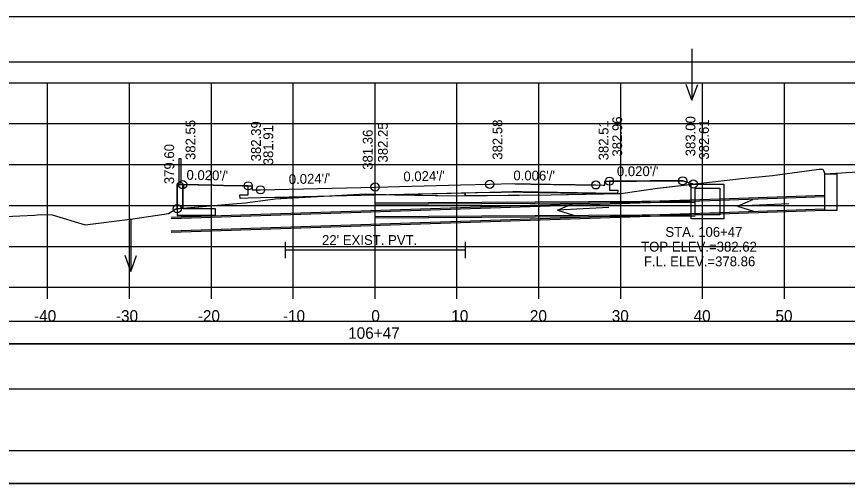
# Model space of a CAD drawing. Extents: x -37291014 to -37290680, y -936053 to -933067.
# Drawn here: x -37290886.9 to -37290785.4, y -934559.9 to -934502.9 of the extents above; entities that cross this region are included whole.
import ezdxf

# ---------------------------------------------------------------- set-up
doc = ezdxf.new("R2010")
doc.units = 0
for name, color, linetype in [('Default', 7, 'Continuous'), ('R_Alt Surface', 7, 'Continuous'), ('R_Axis', 7, 'Continuous'), ('R_Axis Annot', 7, 'Continuous'), ('R_Border', 7, 'Continuous'), ('R_Contours', 7, 'Continuous'), ('R_Exist Surface', 7, 'Continuous'), ('R_Fin Surface', 7, 'Continuous'), ('R_Grid', 7, 'Continuous'), ('R_No Plot', 7, 'Continuous'), ('R_Water', 7, 'Continuous'), ('R_Water Annot', 7, 'Continuous'), ('R_Xsect Elev', 7, 'Continuous'), ('R_Xsect Slope', 7, 'Continuous')]:
    doc.layers.add(name, color=color, linetype=linetype)

msp = doc.modelspace()

# ---------------------------------------------------------------- linework, layer by layer
at = {"layer": 'Default'}
for p, q in [((-37290867.02, -934523.22), (-37290867.02, -934520.22)), ((-37290867.02, -934520.22), (-37290866.85, -934520.22)), ((-37290866.85, -934520.22), (-37290866.85, -934523.22)), ((-37290867.21, -934523.24), (-37290867.27, -934523.3)), ((-37290867.27, -934523.3), (-37290867.27, -934527.19)), ((-37290866.66, -934523.22), (-37290867.21, -934523.22)), ((-37290867.21, -934523.22), (-37290867.21, -934523.24)), ((-37290866.66, -934523.24), (-37290867.21, -934523.24)), ((-37290866.66, -934523.24), (-37290866.66, -934523.22)), ((-37290866.6, -934523.3), (-37290866.66, -934523.24)), ((-37290866.6, -934526.36), (-37290866.6, -934523.3)), ((-37290862.6, -934526.36), (-37290866.6, -934526.36)), ((-37290862.6, -934527.19), (-37290862.6, -934526.36)), ((-37290862.6, -934527.19), (-37290867.27, -934527.19))]:
    msp.add_line(p, q, dxfattribs=at)
for points in [[(-37290992.58, -934508.41), (-37290694.16, -934508.41), (-37290694.16, -934502.89), (-37290992.58, -934502.89)], [(-37290992.31, -934542.86), (-37290693.89, -934542.86), (-37290693.89, -934540.16), (-37290992.31, -934540.16)], [(-37290992.31, -934548.39), (-37290693.89, -934548.39), (-37290693.89, -934542.86), (-37290992.31, -934542.86)]]:
    msp.add_lwpolyline(points, close=True, dxfattribs=at)
msp.add_lwpolyline([(-37290866.52, -934523.91), (-37290866.6, -934523.91), (-37290866.6, -934523.41), (-37290866.52, -934523.41), (-37290866.52, -934523.91)], dxfattribs=at)
at = {"layer": 'R_Alt Surface'}
for points in [[(-37290829.1, -934524.37), (-37290843.1, -934524.71), (-37290857.1, -934525.05), (-37290858.6, -934525.08), (-37290859.6, -934525.1), (-37290859.61, -934524.68), (-37290858.6, -934524.66), (-37290858.6, -934523.57)], [(-37290826.27, -934524.29), (-37290826.27, -934524.29), (-37290826.27, -934524.29), (-37290826.27, -934524.29), (-37290826.27, -934524.29), (-37290829.1, -934524.37), (-37290843.1, -934524.71), (-37290857.1, -934525.05), (-37290858.6, -934525.08), (-37290859.6, -934525.1), (-37290859.61, -934524.68), (-37290858.6, -934524.66), (-37290858.6, -934523.57)], [(-37290814.47, -934522.99), (-37290814.47, -934524.09), (-37290813.46, -934524.11), (-37290813.47, -934524.52), (-37290814.48, -934524.5)], [(-37290829.1, -934524.37), (-37290826.27, -934524.29), (-37290826, -934524.3), (-37290825.78, -934524.3), (-37290825.77, -934524.3), (-37290825.59, -934524.3), (-37290825.49, -934524.31), (-37290825.47, -934524.31), (-37290825.18, -934524.31), (-37290825.12, -934524.31), (-37290825.01, -934524.32), (-37290824.82, -934524.32), (-37290824.62, -934524.32), (-37290824.42, -934524.33), (-37290824.17, -934524.33), (-37290824.06, -934524.34), (-37290823.97, -934524.34), (-37290823.47, -934524.35), (-37290823.46, -934524.35), (-37290823.25, -934524.35), (-37290823.22, -934524.35), (-37290822.92, -934524.36), (-37290822.8, -934524.36), (-37290822.32, -934524.37), (-37290822.26, -934524.37), (-37290822.08, -934524.37), (-37290821.66, -934524.38), (-37290821.3, -934524.39), (-37290821.17, -934524.39), (-37290820.94, -934524.39), (-37290820.82, -934524.39), (-37290820.46, -934524.4), (-37290820.15, -934524.4), (-37290819.99, -934524.41), (-37290819.55, -934524.41), (-37290819.29, -934524.42), (-37290818.71, -934524.42), (-37290818.57, -934524.43), (-37290818.36, -934524.43), (-37290817.51, -934524.44), (-37290817.35, -934524.44), (-37290817.32, -934524.44), (-37290816.38, -934524.45), (-37290816.25, -934524.45), (-37290816.14, -934524.45), (-37290814.48, -934524.5)], [(-37290854.1, -934530.39), (-37290854.1, -934532.39)], [(-37290832.1, -934530.39), (-37290832.1, -934532.39)], [(-37290854.1, -934531.39), (-37290832.1, -934531.39)]]:
    msp.add_lwpolyline(points, dxfattribs=at)
at = {"layer": 'R_Axis'}
for p, q in [((-37290993.1, -934535.96), (-37290693.1, -934535.96)), ((-37290883.1, -934537.36), (-37290883.1, -934535.96)), ((-37290873.1, -934537.36), (-37290873.1, -934535.96)), ((-37290863.1, -934537.36), (-37290863.1, -934535.96)), ((-37290853.1, -934537.36), (-37290853.1, -934535.96)), ((-37290843.1, -934537.36), (-37290843.1, -934535.96)), ((-37290833.1, -934537.36), (-37290833.1, -934535.96)), ((-37290823.1, -934537.36), (-37290823.1, -934535.96)), ((-37290813.1, -934537.36), (-37290813.1, -934535.96)), ((-37290803.1, -934537.36), (-37290803.1, -934535.96)), ((-37290793.1, -934537.36), (-37290793.1, -934535.96))]:
    msp.add_line(p, q, dxfattribs=at)
at = {"layer": 'R_Border'}
msp.add_line((-37290684.92, -934555.96), (-37291001.1, -934555.96), dxfattribs=at)
at = {"layer": 'R_Contours'}
for p, q in [((-37290866.6, -934523.91), (-37290866.6, -934526.3)), ((-37290854.1, -934525.09), (-37290850.22, -934524.88)), ((-37290850.22, -934524.88), (-37290854.1, -934524.97)), ((-37290832.1, -934524.45), (-37290840.69, -934524.65)), ((-37290829.1, -934524.37), (-37290832.1, -934524.45)), ((-37290832.1, -934524.76), (-37290832.1, -934524.45)), ((-37290832.1, -934524.45), (-37290832.1, -934524.76)), ((-37290813.97, -934524.51), (-37290814.48, -934524.5)), ((-37290813.47, -934524.5), (-37290813.97, -934524.51)), ((-37290813.97, -934524.51), (-37290813.47, -934524.52)), ((-37290813.47, -934524.5), (-37290813.09, -934524.5)), ((-37290813.47, -934524.52), (-37290813.47, -934524.5)), ((-37290854.1, -934524.97), (-37290854.1, -934525.09)), ((-37290854.1, -934525.09), (-37290854.1, -934524.97)), ((-37290866.6, -934526.3), (-37290867.27, -934526.36)), ((-37290866.6, -934526.36), (-37290866.6, -934526.3)), ((-37290862.6, -934526.36), (-37290866.6, -934526.36)), ((-37290862.6, -934527.19), (-37290862.6, -934526.36)), ((-37290867.27, -934527.19), (-37290862.6, -934527.19))]:
    msp.add_line(p, q, dxfattribs=at)
for points in [[(-37290866.52, -934523.41), (-37290866.52, -934523.91), (-37290866.6, -934523.91)], [(-37290858.6, -934523.57), (-37290859.35, -934523.55), (-37290861.6, -934523.51), (-37290862.85, -934523.48), (-37290866.52, -934523.41)], [(-37290854.1, -934524.97), (-37290857.1, -934525.05), (-37290858.6, -934525.08), (-37290859.6, -934525.1), (-37290859.61, -934524.68), (-37290858.6, -934524.66), (-37290858.6, -934523.57)], [(-37290804.25, -934523.35), (-37290804.3, -934523.33), (-37290804.39, -934523.3), (-37290804.4, -934523.3), (-37290804.47, -934523.28), (-37290804.49, -934523.27), (-37290805.26, -934523.04), (-37290805.52, -934522.95), (-37290808.25, -934522.97), (-37290808.32, -934522.97), (-37290808.48, -934522.97), (-37290808.88, -934522.97), (-37290809.51, -934522.97), (-37290811.16, -934522.98), (-37290812.1, -934522.98), (-37290812.27, -934522.98), (-37290812.33, -934522.98), (-37290812.59, -934522.98), (-37290812.66, -934522.99), (-37290814.47, -934522.99)], [(-37290814.47, -934522.99), (-37290814.47, -934524.09), (-37290813.46, -934524.11), (-37290813.47, -934524.5)], [(-37290813.09, -934524.5), (-37290808.6, -934523.86), (-37290804.25, -934523.35)], [(-37290804.25, -934523.35), (-37290804.25, -934523.35)], [(-37290840.69, -934524.65), (-37290833.31, -934524.77), (-37290832.1, -934524.76)], [(-37290832.1, -934524.76), (-37290821.61, -934524.66), (-37290813.97, -934524.51)], [(-37290814.48, -934524.5), (-37290816.14, -934524.45), (-37290816.25, -934524.45), (-37290816.38, -934524.45), (-37290817.32, -934524.44), (-37290817.35, -934524.44), (-37290817.51, -934524.44), (-37290818.36, -934524.43), (-37290818.57, -934524.43), (-37290818.71, -934524.42), (-37290819.29, -934524.42), (-37290819.55, -934524.41), (-37290819.99, -934524.41), (-37290820.15, -934524.4), (-37290820.46, -934524.4), (-37290820.82, -934524.39), (-37290820.94, -934524.39), (-37290821.17, -934524.39), (-37290821.3, -934524.39), (-37290821.66, -934524.38), (-37290822.08, -934524.37), (-37290822.26, -934524.37), (-37290822.32, -934524.37), (-37290822.8, -934524.36), (-37290822.92, -934524.36), (-37290823.22, -934524.35), (-37290823.25, -934524.35), (-37290823.46, -934524.35), (-37290823.47, -934524.35), (-37290823.97, -934524.34), (-37290824.06, -934524.34), (-37290824.17, -934524.33), (-37290824.42, -934524.33), (-37290824.62, -934524.32), (-37290824.82, -934524.32), (-37290825.01, -934524.32), (-37290825.12, -934524.31), (-37290825.18, -934524.31), (-37290825.47, -934524.31), (-37290825.49, -934524.31), (-37290825.59, -934524.3), (-37290825.78, -934524.3), (-37290826, -934524.3), (-37290826.27, -934524.29), (-37290829.1, -934524.37)], [(-37290866.6, -934526.3), (-37290859.98, -934525.72), (-37290858.87, -934525.63), (-37290858.63, -934525.6), (-37290855.31, -934525.15), (-37290854.1, -934525.09)], [(-37290867.27, -934526.36), (-37290867.27, -934526.45), (-37290867.27, -934527.19)]]:
    msp.add_lwpolyline(points, dxfattribs=at)
at = {"layer": 'R_Exist Surface'}
msp.add_lwpolyline([(-37290894.61, -934527.59), (-37290884.69, -934527.15), (-37290884.37, -934527.12), (-37290883.88, -934527.06), (-37290882.54, -934527.09), (-37290878.52, -934528.35), (-37290872.71, -934527.59), (-37290868.33, -934526.95), (-37290867.44, -934526.37), (-37290859.98, -934525.72), (-37290858.87, -934525.63), (-37290858.63, -934525.6), (-37290855.31, -934525.15), (-37290846.46, -934524.68), (-37290844.27, -934524.56), (-37290841.75, -934524.64), (-37290833.31, -934524.77), (-37290821.61, -934524.66), (-37290813.09, -934524.5), (-37290808.6, -934523.86), (-37290798.33, -934522.67), (-37290794.55, -934522.29), (-37290788.87, -934521.54), (-37290788.72, -934521.54), (-37290788.39, -934521.54), (-37290788.31, -934521.7), (-37290788.17, -934522.1), (-37290782.17, -934521.71)], dxfattribs=at)
msp.add_lwpolyline([(-37290894.61, -934527.59), (-37290884.69, -934527.15), (-37290884.37, -934527.12), (-37290883.88, -934527.06), (-37290882.54, -934527.09), (-37290878.52, -934528.35), (-37290872.71, -934527.59), (-37290868.33, -934526.95), (-37290867.44, -934526.37), (-37290859.98, -934525.72), (-37290858.87, -934525.63), (-37290858.63, -934525.6), (-37290855.31, -934525.15), (-37290846.46, -934524.68), (-37290844.27, -934524.56), (-37290841.75, -934524.64), (-37290833.31, -934524.77), (-37290821.61, -934524.66), (-37290813.09, -934524.5), (-37290808.6, -934523.86), (-37290798.33, -934522.67), (-37290794.55, -934522.29), (-37290788.87, -934521.54), (-37290788.72, -934521.54), (-37290788.39, -934521.54), (-37290788.31, -934521.7), (-37290788.17, -934522.1), (-37290782.17, -934521.71)], dxfattribs=at)
at = {"layer": 'R_Fin Surface'}
for points in [[(-37290867.27, -934526.45), (-37290867.27, -934525.6), (-37290867.27, -934523.41), (-37290866.77, -934523.41), (-37290866.6, -934523.41), (-37290862.85, -934523.48), (-37290861.6, -934523.51), (-37290859.35, -934523.55), (-37290858.6, -934523.57), (-37290858.48, -934523.57), (-37290858.1, -934523.57), (-37290858.1, -934523.69), (-37290858.1, -934524.07), (-37290857.35, -934524.05), (-37290857.1, -934524.05), (-37290846.61, -934523.8), (-37290843.1, -934523.71), (-37290832.61, -934523.46), (-37290829.1, -934523.37)], [(-37290829.1, -934523.37), (-37290826.27, -934523.29), (-37290826, -934523.3), (-37290825.78, -934523.3), (-37290825.77, -934523.3), (-37290825.59, -934523.3), (-37290825.5, -934523.31), (-37290825.47, -934523.31), (-37290825.18, -934523.31), (-37290825.13, -934523.31), (-37290825.01, -934523.32), (-37290824.82, -934523.32), (-37290824.62, -934523.32), (-37290824.42, -934523.33), (-37290824.17, -934523.33), (-37290824.06, -934523.34), (-37290823.97, -934523.34), (-37290823.47, -934523.35), (-37290823.46, -934523.35), (-37290823.25, -934523.35), (-37290823.22, -934523.35), (-37290822.92, -934523.36), (-37290822.8, -934523.36), (-37290822.32, -934523.37), (-37290822.26, -934523.37), (-37290822.08, -934523.37), (-37290821.66, -934523.38), (-37290821.3, -934523.39), (-37290821.17, -934523.39), (-37290820.94, -934523.39), (-37290820.82, -934523.39), (-37290820.46, -934523.4), (-37290820.15, -934523.4), (-37290819.99, -934523.41), (-37290819.55, -934523.41), (-37290819.29, -934523.42), (-37290818.71, -934523.42), (-37290818.57, -934523.43), (-37290818.36, -934523.43), (-37290817.51, -934523.44), (-37290817.35, -934523.44), (-37290817.32, -934523.44), (-37290816.38, -934523.45), (-37290816.25, -934523.45), (-37290816.14, -934523.45), (-37290815.22, -934523.48), (-37290815.03, -934523.49), (-37290815.03, -934523.01), (-37290815.03, -934522.99), (-37290814.95, -934522.99), (-37290814.47, -934522.99), (-37290812.66, -934522.99), (-37290812.59, -934522.98), (-37290812.33, -934522.98), (-37290812.27, -934522.98), (-37290812.1, -934522.98), (-37290811.16, -934522.98), (-37290809.51, -934522.97), (-37290808.88, -934522.97), (-37290808.48, -934522.97), (-37290808.32, -934522.97), (-37290808.25, -934522.97), (-37290805.52, -934522.95), (-37290805.26, -934523.04), (-37290804.49, -934523.27), (-37290804.47, -934523.28), (-37290804.4, -934523.3), (-37290804.39, -934523.3), (-37290804.3, -934523.33), (-37290804.25, -934523.35), (-37290804.23, -934523.35)]]:
    msp.add_lwpolyline(points, dxfattribs=at)
at = {"layer": 'R_Grid'}
for p, q in [((-37290993.1, -934510.96), (-37290693.1, -934510.96)), ((-37290883.1, -934535.96), (-37290883.1, -934510.96)), ((-37290873.1, -934535.96), (-37290873.1, -934510.96)), ((-37290863.1, -934535.96), (-37290863.1, -934510.96)), ((-37290853.1, -934535.96), (-37290853.1, -934510.96)), ((-37290843.1, -934535.96), (-37290843.1, -934510.96)), ((-37290833.1, -934535.96), (-37290833.1, -934510.96)), ((-37290823.1, -934535.96), (-37290823.1, -934510.96)), ((-37290813.1, -934535.96), (-37290813.1, -934510.96)), ((-37290803.1, -934535.96), (-37290803.1, -934510.96)), ((-37290793.1, -934535.96), (-37290793.1, -934510.96)), ((-37290993.1, -934515.96), (-37290693.1, -934515.96)), ((-37290993.1, -934520.96), (-37290693.1, -934520.96)), ((-37290993.1, -934525.96), (-37290693.1, -934525.96)), ((-37290993.1, -934530.96), (-37290693.1, -934530.96)), ((-37290993.1, -934535.96), (-37290693.1, -934535.96))]:
    msp.add_line(p, q, dxfattribs=at)
at = {"layer": 'R_No Plot'}
for p, q in [((-37290788.16, -934524.75), (-37290800.99, -934525.18)), ((-37290800.99, -934525.18), (-37290868.02, -934527.45)), ((-37290803.99, -934525.43), (-37290843.1, -934525.68)), ((-37290788.16, -934526.58), (-37290800.99, -934527.01)), ((-37290800.99, -934527.01), (-37290868.02, -934529.28)), ((-37290803.99, -934527.26), (-37290843.1, -934527.52)), ((-37291013.5, -934559.94), (-37290680.17, -934559.94))]:
    msp.add_line(p, q, dxfattribs=at)
for points in [[(-37291013.51, -934346.6), (-37290680.17, -934346.6), (-37290680.17, -934559.94), (-37291013.51, -934559.94)], [(-37290767.18, -934350.5), (-37290747.56, -934350.5), (-37290747.56, -934360.38), (-37290731.45, -934360.38), (-37290708.25, -934360.38), (-37290708.25, -934384.71), (-37290684.92, -934384.71), (-37290684.92, -934555.96), (-37291001.1, -934555.96), (-37291001.1, -934350.5)]]:
    msp.add_lwpolyline(points, close=True, dxfattribs=at)
for centre in [(-37290866.6, -934523.41), (-37290829.1, -934523.37), (-37290829.1, -934523.37), (-37290814.47, -934522.99), (-37290805.52, -934522.95), (-37290804.23, -934523.35), (-37290858.6, -934523.57), (-37290857.1, -934524.05), (-37290843.1, -934523.71), (-37290816.14, -934523.45), (-37290867.27, -934526.36)]:
    msp.add_circle(centre, 0.5, dxfattribs=at)
at = {"layer": 'R_Water'}
for p, q in [((-37290788.16, -934524.91), (-37290800.99, -934525.35)), ((-37290800.99, -934525.35), (-37290868.02, -934527.61)), ((-37290803.99, -934525.6), (-37290843.1, -934525.85)), ((-37290800.99, -934526.85), (-37290868.02, -934529.11)), ((-37290788.16, -934526.41), (-37290800.99, -934526.85)), ((-37290803.99, -934527.1), (-37290843.1, -934527.35))]:
    msp.add_line(p, q, dxfattribs=at)
for points in [[(-37290788.16, -934522.1), (-37290786.68, -934522.1), (-37290786.68, -934526.58), (-37290788.16, -934526.58)], [(-37290802.49, -934523.34), (-37290800.49, -934523.34), (-37290800.49, -934527.6), (-37290802.49, -934527.6), (-37290804.49, -934527.6), (-37290804.49, -934523.34)], [(-37290802.49, -934523.84), (-37290800.99, -934523.84), (-37290800.99, -934527.1), (-37290802.49, -934527.1), (-37290803.99, -934527.1), (-37290803.99, -934523.84)]]:
    msp.add_lwpolyline(points, close=True, dxfattribs=at)
at = {"layer": 'R_Water Annot'}
for p, q in [((-37290804.39, -934506.83), (-37290804.39, -934513.11)), ((-37290804.39, -934513.11), (-37290805.09, -934511.19)), ((-37290804.39, -934513.11), (-37290803.69, -934511.19)), ((-37290820.83, -934526.53), (-37290818.95, -934525.73)), ((-37290798.83, -934526.03), (-37290796.94, -934525.25)), ((-37290792.56, -934525.78), (-37290798.83, -934526.03)), ((-37290814.56, -934526.2), (-37290820.83, -934526.53)), ((-37290820.83, -934526.53), (-37290818.87, -934527.13)), ((-37290798.83, -934526.03), (-37290796.89, -934526.65)), ((-37290872.94, -934527.73), (-37290872.94, -934534.02)), ((-37290872.94, -934534.02), (-37290873.64, -934532.09)), ((-37290872.94, -934534.02), (-37290872.24, -934532.09))]:
    msp.add_line(p, q, dxfattribs=at)
at = {"layer": 'R_Xsect Elev'}
msp.add_line((-37290843.1, -934524.6), (-37290843.1, -934514.6), dxfattribs=at)
msp.add_line((-37290843.1, -934524.6), (-37290843.1, -934514.6), dxfattribs=at)

# ---------------------------------------------------------------- texts
at = {"layer": 'R_Axis Annot'}
for s, p in [('-40', (-37290884.76, -934540.16)), ('-30', (-37290874.76, -934540.16)), ('-20', (-37290864.76, -934540.16)), ('-10', (-37290854.36, -934540.16)), ('0', (-37290843.56, -934540.16)), ('10', (-37290833.79, -934540.16)), ('20', (-37290824.19, -934540.16)), ('30', (-37290814.19, -934540.16)), ('40', (-37290804.19, -934540.16)), ('50', (-37290794.19, -934540.16)), ('106+47', (-37290846.39, -934542.26))]:
    msp.add_text(s, height=1.4, dxfattribs=at).set_placement(p)
at = {"layer": 'R_Water'}
msp.add_text("22' EXIST. PVT.", height=1.2, dxfattribs=at).set_placement((-37290849.58, -934530.79))
at = {"layer": 'R_Water Annot'}
for s, p in [('STA. 106+47', (-37290807.64, -934529.8)), ('TOP ELEV.=382.62', (-37290810.6, -934531.6)), ('F.L. ELEV.=378.86', (-37290810.26, -934533.4))]:
    msp.add_text(s, height=1.2, dxfattribs=at).set_placement(p)
at = {"layer": 'R_Xsect Elev'}
for s, rotation, p in [('382.55', 90, (-37290865.05, -934520.41)), ('382.39', 90, (-37290857.05, -934520.57)), ('382.58', 90, (-37290827.55, -934520.37)), ('382.51', 90, (-37290814.59, -934520.45)), ('382.96', 90, (-37290812.92, -934519.99)), ('383.00', 90, (-37290803.97, -934519.95)), ('382.61', 90, (-37290802.32, -934520.35)), ('381.91', 90, (-37290855.55, -934521.05)), ('381.36', 90, (-37290843.4, -934521.6)), ('381.36', 90, (-37290843.4, -934521.6)), ('382.25', 90, (-37290841.55, -934520.71)), ('379.60', 90, (-37290867.65, -934523.36)), ("0.006'/'", 359.6589, (-37290826.21, -934522.89))]:
    msp.add_text(s, height=1.2, rotation=rotation, dxfattribs=at).set_placement(p)
at = {"layer": 'R_Xsect Slope'}
for s, rotation, p in [("0.020'/'", 358.8542, (-37290866.15, -934522.82)), ("0.020'/'", 358.8542, (-37290866.15, -934522.82)), ("0.024'/'", 1.3748, (-37290839.63, -934523.03)), ("0.024'/'", 1.3748, (-37290839.63, -934523.03)), ("0.020'/'", 0.2489, (-37290813.56, -934522.39)), ("0.024'/'", 1.3748, (-37290853.63, -934523.36)), ("0.024'/'", 1.3748, (-37290853.63, -934523.36))]:
    msp.add_text(s, height=1.2, rotation=rotation, dxfattribs=at).set_placement(p)

doc.saveas('drawing.dxf')
